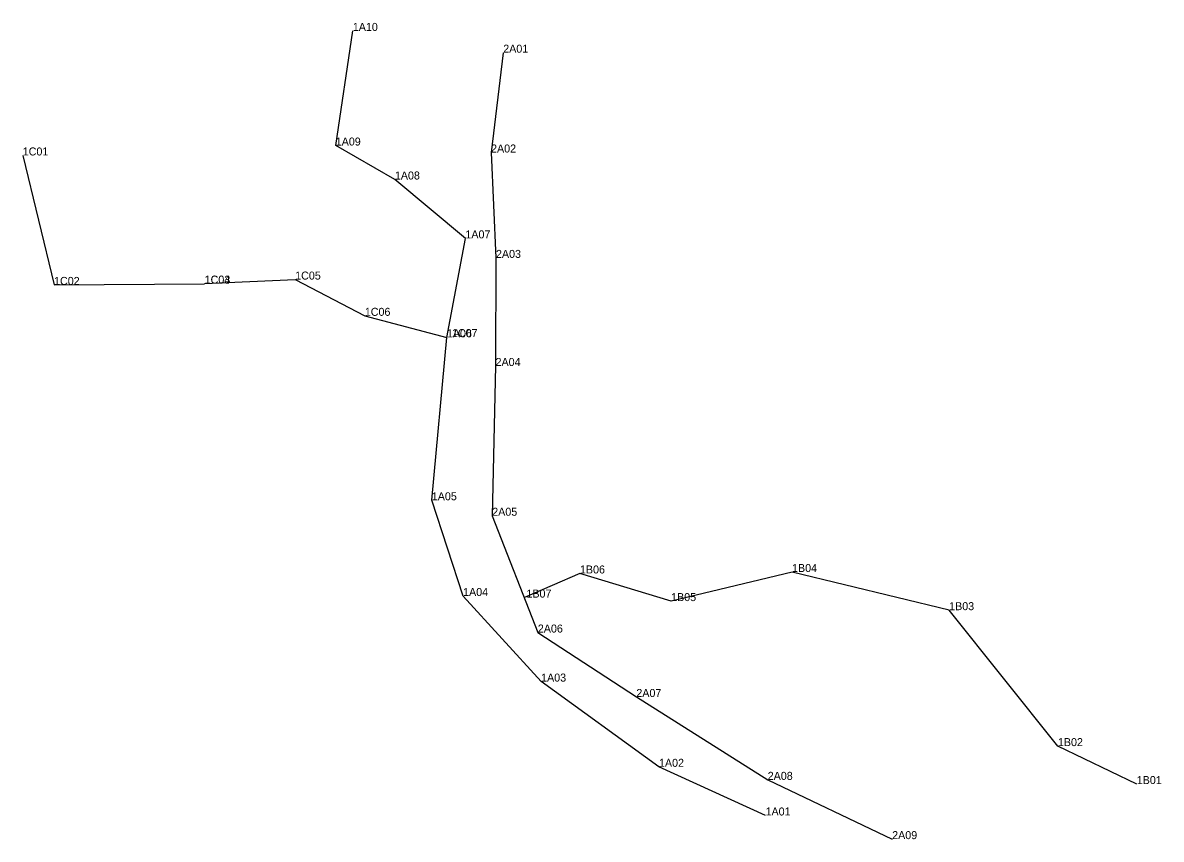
# Model space of a CAD drawing. Extents: x 2192535 to 2192890, y 863798 to 864053.
import ezdxf

# ---------------------------------------------------------------- set-up
doc = ezdxf.new("R2010")
doc.units = 0
for name, color, linetype in [('S_Wetland_Palustrine_Forested', 7, 'Continuous'), ('S_Wetland_PalustrineScrubShrub', 7, 'Continuous'), ('S_Wetland_RiverineUnconsSubstr', 7, 'Continuous')]:
    doc.layers.add(name, color=color, linetype=linetype)

msp = doc.modelspace()

# ---------------------------------------------------------------- linework, layer by layer
at = {"layer": 'S_Wetland_Palustrine_Forested'}
msp.add_lwpolyline([(2192534.59, 864011.72), (2192544.37, 863971.28), (2192591.4, 863971.66)], dxfattribs=at)
at = {"layer": 'S_Wetland_PalustrineScrubShrub'}
for points in [[(2192591.39, 863971.7), (2192619.67, 863972.95), (2192641.42, 863961.63), (2192667.06, 863954.89)], [(2192882.5, 863815.37), (2192857.88, 863827.22), (2192823.91, 863869.68), (2192774.85, 863881.6), (2192737.08, 863872.52), (2192708.61, 863881.15), (2192691.29, 863873.68)]]:
    msp.add_lwpolyline(points, dxfattribs=at)
at = {"layer": 'S_Wetland_RiverineUnconsSubstr'}
for points in [[(2192766.57, 863805.55), (2192733.29, 863820.75), (2192696.48, 863847.38), (2192672.12, 863874.11), (2192662.34, 863904.01), (2192667.06, 863954.89), (2192672.83, 863985.82), (2192650.81, 864004.21), (2192632.34, 864014.82), (2192637.67, 864050.63)], [(2192684.65, 864043.82), (2192680.85, 864012.64), (2192682.38, 863979.72), (2192682.25, 863945.96), (2192681.21, 863899.18), (2192695.46, 863862.69), (2192726.22, 863842.57), (2192767.25, 863816.68), (2192806.12, 863798.17)]]:
    msp.add_lwpolyline(points, dxfattribs=at)

# ---------------------------------------------------------------- texts
at = {"layer": 'S_Wetland_Palustrine_Forested'}
for s, p in [('1C01', (2192534.59, 864011.72)), ('1C03', (2192591.4, 863971.66)), ('1C02', (2192544.37, 863971.28))]:
    msp.add_text(s, height=2.5, dxfattribs=at).set_placement(p)
at = {"layer": 'S_Wetland_PalustrineScrubShrub'}
for s, p in [('1C04', (2192591.39, 863971.7)), ('1C05', (2192619.67, 863972.95)), ('1C06', (2192641.42, 863961.63)), ('1C07', (2192668.62, 863954.99)), ('1B06', (2192708.61, 863881.15)), ('1B04', (2192774.85, 863881.6)), ('1B07', (2192691.89, 863873.61)), ('1B05', (2192737.08, 863872.52)), ('1B03', (2192823.91, 863869.68)), ('1B02', (2192857.88, 863827.22)), ('1B01', (2192882.5, 863815.37))]:
    msp.add_text(s, height=2.5, dxfattribs=at).set_placement(p)
at = {"layer": 'S_Wetland_RiverineUnconsSubstr'}
for s, p in [('1A10', (2192637.67, 864050.63)), ('2A01', (2192684.65, 864043.82)), ('1A09', (2192632.34, 864014.82)), ('2A02', (2192680.85, 864012.64)), ('1A08', (2192650.81, 864004.21)), ('1A07', (2192672.83, 863985.82)), ('2A03', (2192682.38, 863979.72)), ('1A06', (2192667.06, 863954.89)), ('2A04', (2192682.25, 863945.96)), ('1A05', (2192662.34, 863904.01)), ('2A05', (2192681.21, 863899.18)), ('1A04', (2192672.12, 863874.11)), ('2A06', (2192695.46, 863862.69)), ('1A03', (2192696.48, 863847.38)), ('2A07', (2192726.22, 863842.57)), ('1A02', (2192733.29, 863820.75)), ('2A08', (2192767.25, 863816.68)), ('1A01', (2192766.57, 863805.55)), ('2A09', (2192806.12, 863798.17))]:
    msp.add_text(s, height=2.5, dxfattribs=at).set_placement(p)

doc.saveas('drawing.dxf')
